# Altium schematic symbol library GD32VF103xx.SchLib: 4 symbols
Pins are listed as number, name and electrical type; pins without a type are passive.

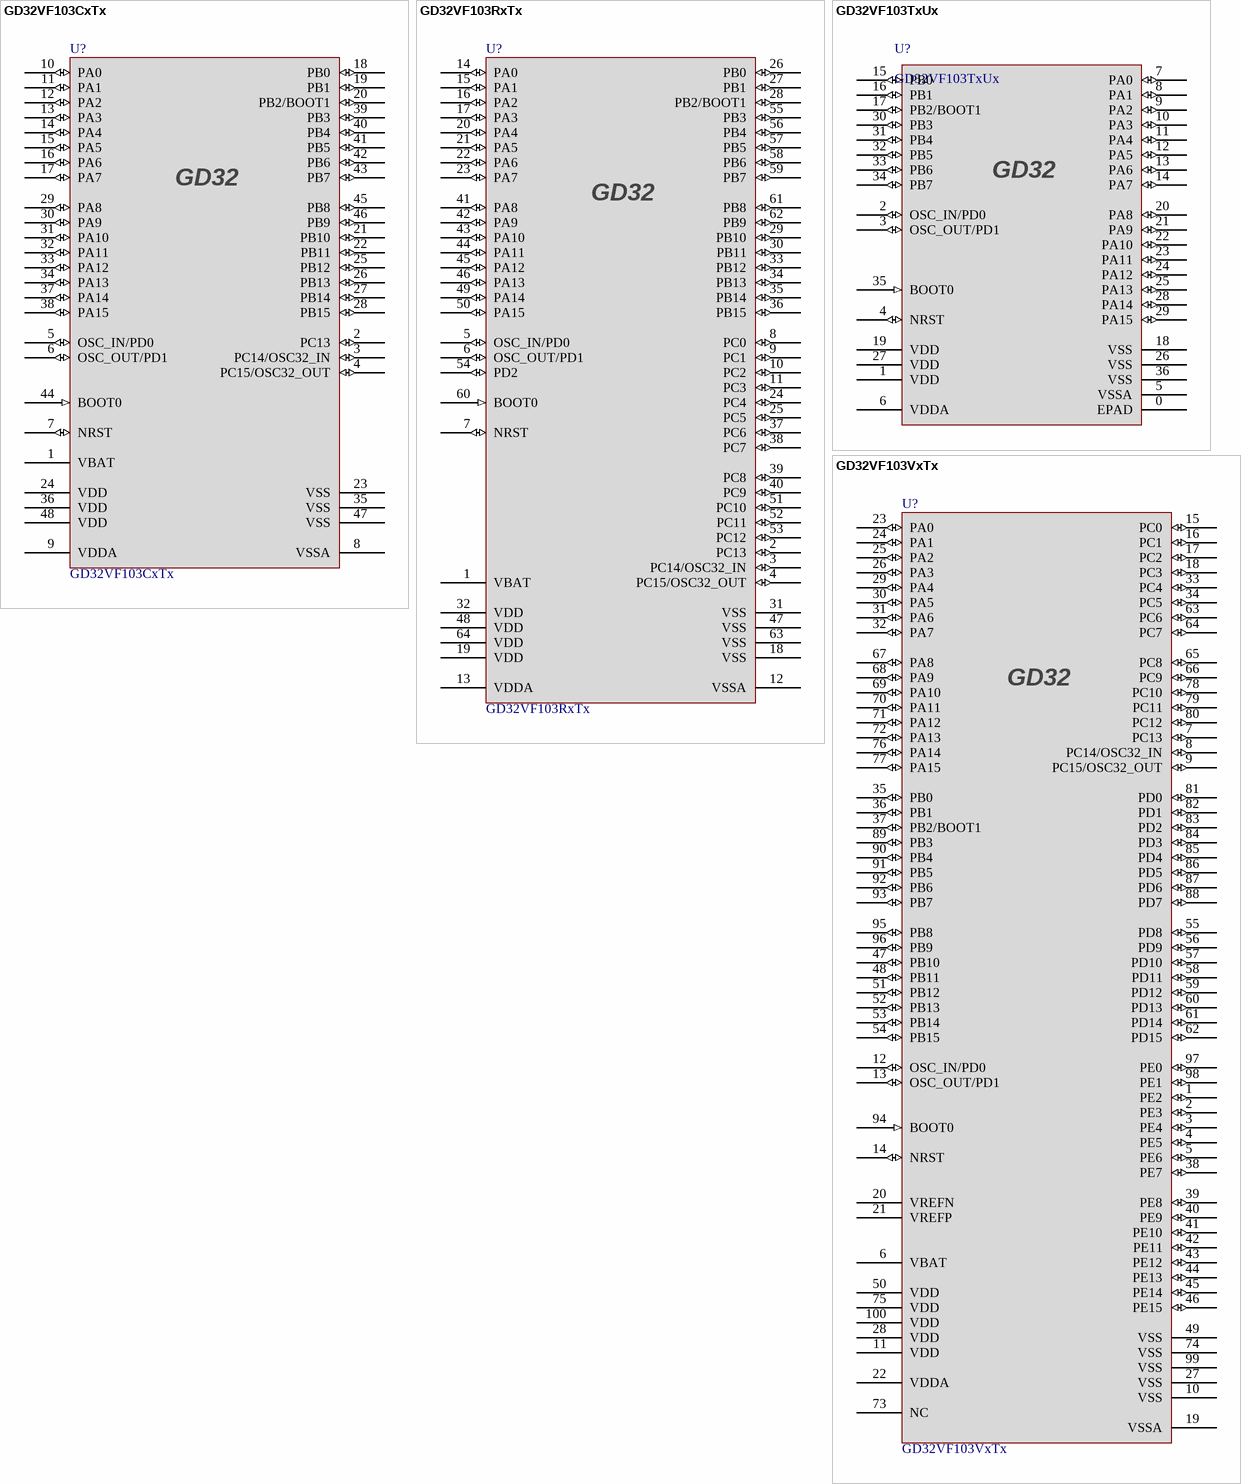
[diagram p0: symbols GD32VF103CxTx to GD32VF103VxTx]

## GD32VF103CxTx
designator U?
footprint LQFP48_7x7x1.6
pins: 1 VBAT (power), 2 PC13 (io), 3 PC14/OSC32_IN (io), 4 PC15/OSC32_OUT (io), 5 OSC_IN/PD0 (io), 6 OSC_OUT/PD1 (io), 7 NRST (io), 8 VSSA (power), 9 VDDA (power), 10 PA0 (io), 11 PA1 (io), 12 PA2 (io), 13 PA3 (io), 14 PA4 (io), 15 PA5 (io), 16 PA6 (io), 17 PA7 (io), 18 PB0 (io), 19 PB1 (io), 20 PB2/BOOT1 (io), 21 PB10 (io), 22 PB11 (io), 23 VSS (power), 24 VDD (power), 25 PB12 (io), 26 PB13 (io), 27 PB14 (io), 28 PB15 (io), 29 PA8 (io), 30 PA9 (io), 31 PA10 (io), 32 PA11 (io), 33 PA12 (io), 34 PA13 (io), 35 VSS (power), 36 VDD (power), 37 PA14 (io), 38 PA15 (io), 39 PB3 (io), 40 PB4 (io), 41 PB5 (io), 42 PB6 (io), 43 PB7 (io), 44 BOOT0 (in), 45 PB8 (io), 46 PB9 (io), 47 VSS (power), 48 VDD (power)
2 alternate drawings of the same symbol

## GD32VF103RxTx
designator U?
footprint LQPF64_10x10x1.6
pins: 1 VBAT (power), 2 PC13 (io), 3 PC14/OSC32_IN (io), 4 PC15/OSC32_OUT (io), 5 OSC_IN/PD0 (io), 6 OSC_OUT/PD1 (io), 7 NRST (io), 8 PC0 (io), 9 PC1 (io), 10 PC2 (io), 11 PC3 (io), 12 VSSA (power), 13 VDDA (power), 14 PA0 (io), 15 PA1 (io), 16 PA2 (io), 17 PA3 (io), 18 VSS (power), 19 VDD (power), 20 PA4 (io), 21 PA5 (io), 22 PA6 (io), 23 PA7 (io), 24 PC4 (io), 25 PC5 (io), 26 PB0 (io), 27 PB1 (io), 28 PB2/BOOT1 (io), 29 PB10 (io), 30 PB11 (io), 31 VSS (power), 32 VDD (power), 33 PB12 (io), 34 PB13 (io), 35 PB14 (io), 36 PB15 (io), 37 PC6 (io), 38 PC7 (io), 39 PC8 (io), 40 PC9 (io), 41 PA8 (io), 42 PA9 (io), 43 PA10 (io), 44 PA11 (io), 45 PA12 (io), 46 PA13 (io), 47 VSS (power), 48 VDD (power), 49 PA14 (io), 50 PA15 (io), 51 PC10 (io), 52 PC11 (io), 53 PC12 (io), 54 PD2 (io), 55 PB3 (io), 56 PB4 (io), 57 PB5 (io), 58 PB6 (io), 59 PB7 (io), 60 BOOT0 (in), 61 PB8 (io), 62 PB9 (io), 63 VSS (power), 64 VDD (power)
2 alternate drawings of the same symbol

## GD32VF103TxUx
designator U?
footprint QFN36_6X6X0.9
pins: 0 EPAD (power), 1 VDD (power), 2 OSC_IN/PD0 (io), 3 OSC_OUT/PD1 (io), 4 NRST (io), 5 VSSA (power), 6 VDDA (power), 7 PA0 (io), 8 PA1 (io), 9 PA2 (io), 10 PA3 (io), 11 PA4 (io), 12 PA5 (io), 13 PA6 (io), 14 PA7 (io), 15 PB0 (io), 16 PB1 (io), 17 PB2/BOOT1 (io), 18 VSS (power), 19 VDD (power), 20 PA8 (io), 21 PA9 (io), 22 PA10 (io), 23 PA11 (io), 24 PA12 (io), 25 PA13 (io), 26 VSS (power), 27 VDD (power), 28 PA14 (io), 29 PA15 (io), 30 PB3 (io), 31 PB4 (io), 32 PB5 (io), 33 PB6 (io), 34 PB7 (io), 35 BOOT0 (in), 36 VSS (power)

## GD32VF103VxTx
designator U?
footprint LQFP100_14x14x1.6
pins: 1 PE2 (io), 2 PE3 (io), 3 PE4 (io), 4 PE5 (io), 5 PE6 (io), 6 VBAT (power), 7 PC13 (io), 8 PC14/OSC32_IN (io), 9 PC15/OSC32_OUT (io), 10 VSS (power), 11 VDD (power), 12 OSC_IN/PD0 (io), 13 OSC_OUT/PD1 (io), 14 NRST (io), 15 PC0 (io), 16 PC1 (io), 17 PC2 (io), 18 PC3 (io), 19 VSSA (power), 20 VREFN (power), 21 VREFP (power), 22 VDDA (power), 23 PA0 (io), 24 PA1 (io), 25 PA2 (io), 26 PA3 (io), 27 VSS (power), 28 VDD (power), 29 PA4 (io), 30 PA5 (io), 31 PA6 (io), 32 PA7 (io), 33 PC4 (io), 34 PC5 (io), 35 PB0 (io), 36 PB1 (io), 37 PB2/BOOT1 (io), 38 PE7 (io), 39 PE8 (io), 40 PE9 (io), 41 PE10 (io), 42 PE11 (io), 43 PE12 (io), 44 PE13 (io), 45 PE14 (io), 46 PE15 (io), 47 PB10 (io), 48 PB11 (io), 49 VSS (power), 50 VDD (power), 51 PB12 (io), 52 PB13 (io), 53 PB14 (io), 54 PB15 (io), 55 PD8 (io), 56 PD9 (io), 57 PD10 (io), 58 PD11 (io), 59 PD12 (io), 60 PD13 (io), 61 PD14 (io), 62 PD15 (io), 63 PC6 (io), 64 PC7 (io), 65 PC8 (io), 66 PC9 (io), 67 PA8 (io), 68 PA9 (io), 69 PA10 (io), 70 PA11 (io), 71 PA12 (io), 72 PA13 (io), 73 NC, 74 VSS (power), 75 VDD (power), 76 PA14 (io), 77 PA15 (io), 78 PC10 (io), 79 PC11 (io), 80 PC12 (io), 81 PD0 (io), 82 PD1 (io), 83 PD2 (io), 84 PD3 (io), 85 PD4 (io), 86 PD5 (io), 87 PD6 (io), 88 PD7 (io), 89 PB3 (io), 90 PB4 (io), 91 PB5 (io), 92 PB6 (io), 93 PB7 (io), 94 BOOT0 (in), 95 PB8 (io), 96 PB9 (io), 97 PE0 (io), 98 PE1 (io), 99 VSS (power), 100 VDD (power)
2 alternate drawings of the same symbol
